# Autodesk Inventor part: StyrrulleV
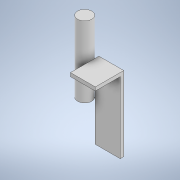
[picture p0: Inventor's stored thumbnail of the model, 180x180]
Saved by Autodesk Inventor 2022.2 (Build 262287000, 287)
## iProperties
Created: 2022-03
Part Number: StyrrulleV
Material: Generic
Document SubType Name: Modeling
Designer: cl
Density: 1 g/cm^3
Appearance: Default
Author: cl
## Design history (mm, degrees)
sketch "Sketch1"
  geometry: L1 (0, 0)-(0, -5); L2 (0, -5)-(105, -5); L3 (105, -5)-(105, 35); L4 (105, 35)-(100, 35); L5 (100, 35)-(100, 0); L6 (100, 0)-(0, 0)
  constraints: 12 end point, 5 perpendicular, 1 vertical
  dimensions: "d0" = 5 distance of L1.start L1.end; "d1" = 5 distance between parallel lines of L3 L5; "d2" = 105 distance of L1.end L2.end; "d3" = 40 distance of L2.end L3.end
extrude "Extrusion1" new body sketch "Sketch1" distance "d4" = 35; taper "d5" = 0 deg
sketch "Sketch2"
  geometry: L1 (0, 40)-(0, 0) reference; L2 (0, 0)-(35, 0) reference; L3 (35, 40)-(35, 0) reference; L4 (0, 40)-(35, 40) reference; C1 r 10 at (-10, 30); 1 further point
  constraints: 2 tangent, 1 centre point
  dimensions: "d6" = 20 diameter of C1
extrude "Extrusion2" join sketch "Sketch2" distance "d7" = 50; taper "d9" = 0 deg; dims "d8" = 50, "d10" = 0
body "Solid1"
node "Projected Loop1"
